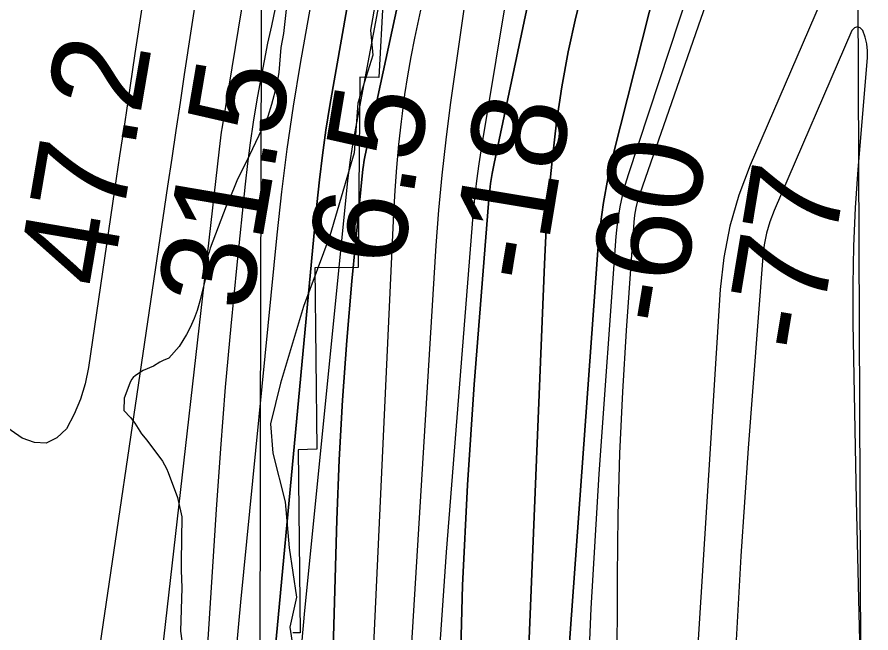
# Model space of a CAD drawing. Extents: x 3187622 to 3225504, y 800805 to 826213.
# Drawn here: x 3196898 to 3197502, y 822602 to 823038 of the extents above; entities that cross this region are included whole.
import ezdxf

# ---------------------------------------------------------------- set-up
doc = ezdxf.new("R2010")
doc.units = 0
for name, color, linetype in [('V-GRID-MAJR', 7, 'Continuous'), ('V-RIVR-EDGE', 7, 'Continuous'), ('V-RIVR-RANG', 7, 'Continuous'), ('V-RRAP-RVMT', 7, 'Continuous'), ('V-SITE-VEGE', 7, 'Continuous'), ('V-TOPO-DPTH', 7, 'Continuous'), ('V-TOPO-MAJR', 7, 'Continuous'), ('V-TOPO-MINR', 7, 'Continuous'), ('V-TOPO-WATR', 7, 'Continuous')]:
    doc.layers.add(name, color=color, linetype=linetype)

msp = doc.modelspace()

# ---------------------------------------------------------------- linework, layer by layer
at = {"layer": 'V-GRID-MAJR'}
msp.add_spline([(3197031.47, 806236.813), (3197045.574, 812297.071), (3197059.682, 818359.272), (3197073.789, 824421.511), (3197073.793, 824423.414)], degree=3, dxfattribs=at)
at = {"layer": 'V-RIVR-EDGE'}
msp.add_lwpolyline([(3197168.0925766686, 823307.4362562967), (3197151.0337839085, 823264.4451984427), (3197147.071178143, 823244.0250751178), (3197150.442182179, 823200.9835002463), (3197156.717268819, 823101.8611295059), (3197155.338001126, 823071.4369970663), (3197147.842091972, 823028.4222929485), (3197149.5367300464, 823010.5962559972), (3197139.0206566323, 822976.7172827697), (3197136.325536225, 822941.5149330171), (3197119.2280495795, 822882.8755201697), (3197100.4133534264, 822832.9339371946), (3197084.195968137, 822778.639139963), (3197077.1702049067, 822749.967686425), (3197078.8573191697, 822729.0989137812), (3197087.4659381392, 822694.7379714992), (3197090.428061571, 822662.1297081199), (3197095.55819349, 822627.3426879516), (3197090.724085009, 822606.055361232), (3197095.002061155, 822578.2253151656)], dxfattribs=at)
at = {"layer": 'V-RRAP-RVMT'}
for p, q in [((3197160.138000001, 823116.417999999), (3197153.893000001, 822994.8849999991)), ((3197495.440000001, 822468.317999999), (3197493.133000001, 823063.8709999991)), ((3197140.277000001, 822995.0219999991), (3197139.165000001, 822860.398999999)), ((3197153.893000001, 822994.8849999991), (3197140.277000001, 822995.0219999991)), ((3197139.165000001, 822860.398999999), (3197108.498000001, 822860.167999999)), ((3197108.498000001, 822860.167999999), (3197109.800000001, 822731.8879999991)), ((3197109.800000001, 822731.8879999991), (3197096.735000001, 822731.5619999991)), ((3197096.735000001, 822731.5619999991), (3197098.137000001, 822602.1149999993)), ((3197098.137000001, 822602.1149999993), (3197092.933000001, 822601.9669999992))]:
    msp.add_line(p, q, dxfattribs=at)
at = {"layer": 'V-SITE-VEGE'}
for p, q in [((3197090.024, 823060.696), (3197086.309, 823025.897)), ((3197086.309, 823025.897), (3197084.38, 823016.175)), ((3197084.38, 823016.175), (3197084.034, 823010.1089999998)), ((3197084.034, 823010.1089999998), (3197082.932, 822998.3740000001)), ((3197082.932, 822998.3740000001), (3197081.4020000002, 822989.061)), ((3197081.4020000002, 822989.061), (3197077.89, 822975.688)), ((3197077.89, 822975.688), (3197075.142, 822967.172)), ((3197075.142, 822967.172), (3197060.079, 822935.498)), ((3197057.697, 822931.029), (3197053.3370000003, 822921.6900000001)), ((3197060.079, 822935.498), (3197057.697, 822931.029)), ((3197053.3370000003, 822921.6900000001), (3197047.805, 822908.296)), ((3197047.805, 822908.296), (3197045.824, 822903.832)), ((3197045.824, 822903.832), (3197034.382, 822874.212)), ((3197033.6, 822871.375), (3197032.418, 822868.1290000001)), ((3197034.382, 822874.212), (3197033.6, 822871.375)), ((3197032.418, 822868.1290000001), (3197032.5100000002, 822858.4280000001)), ((3197032.5100000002, 822858.4280000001), (3197030.954, 822851.946)), ((3197030.954, 822851.946), (3197027.057, 822836.547)), ((3197027.057, 822836.547), (3197025.097, 822830.061)), ((3197025.097, 822830.061), (3197023.129, 822824.382)), ((3197023.129, 822824.382), (3197020.362, 822817.887)), ((3197020.362, 822817.887), (3197017.576, 822813.0089999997)), ((3197017.576, 822813.0089999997), (3197012.401, 822804.471)), ((3197012.401, 822804.471), (3197005.202, 822796.318)), ((3196998.761, 822793.4280000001), (3196994.342, 822790.557)), ((3197001.176, 822794.6630000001), (3196998.761, 822793.4280000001)), ((3197005.202, 822796.318), (3197001.176, 822794.6630000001)), ((3196987.094, 822787.659), (3196981.466, 822783.966)), ((3196994.342, 822790.557), (3196987.094, 822787.659)), ((3196978.666, 822781.109), (3196977.477, 822778.672)), ((3196979.862, 822782.736), (3196978.666, 822781.109)), ((3196981.466, 822783.966), (3196979.862, 822782.736)), ((3196977.477, 822778.672), (3196973.532, 822768.123)), ((3196973.532, 822768.123), (3196973.213, 822759.229)), ((3196973.213, 822759.229), (3196978.109, 822754.424)), ((3196978.109, 822754.424), (3196980.977, 822750.408)), ((3196980.977, 822750.408), (3196985.9, 822742.7729999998)), ((3196985.9, 822742.7729999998), (3196989.58, 822738.362)), ((3196989.58, 822738.362), (3197000.6350000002, 822723.509)), ((3197000.6350000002, 822723.509), (3197003.515, 822718.281)), ((3197003.515, 822718.281), (3197004.754, 822715.4629999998)), ((3197004.754, 822715.4629999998), (3197011.389, 822697.737)), ((3197011.389, 822697.737), (3197014.349, 822684.0219999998)), ((3197014.349, 822684.0219999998), (3197013.839, 822652.485)), ((3197013.839, 822652.485), (3197013.896, 822646.421)), ((3197013.896, 822646.421), (3197014.418, 822633.893)), ((3197014.418, 822633.893), (3197013.497, 822603.161)), ((3197013.497, 822603.161), (3197016.538, 822580.954))]:
    msp.add_line(p, q, dxfattribs=at)
at = {"layer": 'V-TOPO-DPTH'}
for points in [[(3197476.2531391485, 824082.4498993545), (3197400.6026303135, 823848.0940233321), (3197371.423133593, 823752.9000641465), (3197344.1403861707, 823657.1956286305), (3197319.702762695, 823560.7254786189), (3197297.1618885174, 823463.7448522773), (3197270.916225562, 823342.7248028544), (3197262.997966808, 823305.8549675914), (3197255.1788151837, 823268.9643345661), (3197247.5083242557, 823232.0425048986), (3197239.9369404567, 823195.0998774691), (3197232.7720213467, 823158.084515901), (3197226.0496171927, 823120.9930302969), (3197219.9909854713, 823083.7873586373), (3197214.3748687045, 823046.5055629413), (3197204.3212636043, 822975.4624295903), (3197201.1143222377, 822950.6746102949), (3197198.30237618, 822925.8468160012), (3197196.0829230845, 822900.9590592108), (3197194.2584652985, 822876.0313274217), (3197159.798511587, 822313.1102253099)], [(3197476.2531391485, 824082.4498993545), (3197400.6026303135, 823848.0940233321), (3197371.423133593, 823752.9000641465), (3197344.1403861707, 823657.1956286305), (3197319.702762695, 823560.7254786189), (3197297.1618885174, 823463.7448522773), (3197270.916225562, 823342.7248028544), (3197262.997966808, 823305.8549675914), (3197255.1788151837, 823268.9643345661), (3197247.5083242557, 823232.0425048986), (3197239.9369404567, 823195.0998774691), (3197232.7720213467, 823158.084515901), (3197226.0496171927, 823120.9930302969), (3197219.9909854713, 823083.7873586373), (3197214.3748687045, 823046.5055629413), (3197204.3212636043, 822975.4624295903), (3197201.1143222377, 822950.6746102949), (3197198.30237618, 822925.8468160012), (3197196.0829230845, 822900.9590592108), (3197194.2584652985, 822876.0313274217), (3197159.798511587, 822313.1102253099)], [(3197242.8272081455, 822171.8038128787), (3197270.9694217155, 822862.7606196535), (3197272.3360784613, 822887.9559272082), (3197274.154351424, 822913.1124672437), (3197276.6500487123, 822938.210856), (3197279.5973622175, 822963.270477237), (3197283.3806034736, 822988.2016909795), (3197287.8235845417, 823013.0010180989), (3197293.256175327, 823037.6025152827), (3197299.3485059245, 823062.072125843), (3197311.6804694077, 823107.6837639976), (3197324.16746818, 823154.9269685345), (3197336.297293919, 823202.2595570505), (3197347.89136011, 823249.7262215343), (3197359.1282532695, 823297.2822699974), (3197392.6230658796, 823442.7045141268), (3197414.0540988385, 823540.5690377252), (3197434.0696880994, 823638.7063679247), (3197451.962111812, 823737.252908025), (3197468.4390918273, 823836.0722547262), (3197497.127014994, 824020.3690957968)], [(3197497.127014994, 824020.3690957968), (3197468.4390918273, 823836.0722547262), (3197451.962111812, 823737.252908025), (3197434.0696880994, 823638.7063679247), (3197414.0540988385, 823540.5690377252), (3197392.6230658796, 823442.7045141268), (3197359.1282532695, 823297.2822699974), (3197347.89136011, 823249.7262215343), (3197336.297293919, 823202.2595570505), (3197324.16746818, 823154.9269685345), (3197311.6804694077, 823107.6837639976), (3197299.3485059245, 823062.072125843), (3197293.256175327, 823037.6025152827), (3197287.8235845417, 823013.0010180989), (3197283.3806034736, 822988.2016909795), (3197279.5973622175, 822963.270477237), (3197276.6500487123, 822938.210856), (3197274.154351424, 822913.1124672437), (3197272.3360784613, 822887.9559272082), (3197270.9694217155, 822862.7606196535), (3197242.8272081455, 822171.8038128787)], [(3197103.322574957, 821953.4703882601), (3197124.125590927, 822682.0580161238), (3197125.7716292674, 822724.3229395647), (3197128.0017201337, 822766.55093606), (3197131.1078897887, 822808.7235421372), (3197134.7981119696, 822850.8592212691), (3197142.564255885, 822930.0649157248), (3197142.8528429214, 822932.5633014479), (3197143.1985527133, 822935.0527473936), (3197143.6299466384, 822937.5287836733), (3197144.118463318, 822939.9958801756), (3197198.8532792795, 823193.3804697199), (3197227.1892405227, 823322.433536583), (3197256.1079080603, 823451.3538161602), (3197285.900635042, 823580.0749148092), (3197316.27606832, 823708.6632261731), (3197380.5428862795, 823976.6569945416)], [(3197380.5428862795, 823976.6569945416), (3197316.27606832, 823708.6632261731), (3197285.900635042, 823580.0749148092), (3197256.1079080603, 823451.3538161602), (3197227.1892405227, 823322.433536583), (3197198.8532792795, 823193.3804697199), (3197144.118463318, 822939.9958801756), (3197143.6299466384, 822937.5287836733), (3197143.1985527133, 822935.0527473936), (3197142.8528429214, 822932.5633014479), (3197142.564255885, 822930.0649157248), (3197134.7981119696, 822850.8592212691), (3197131.1078897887, 822808.7235421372), (3197128.0017201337, 822766.55093606), (3197125.7716292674, 822724.3229395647), (3197124.125590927, 822682.0580161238), (3197103.322574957, 821953.4703882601)], [(3197281.5857899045, 822497.2418799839), (3197308.8040364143, 822872.4387211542), (3197310.4971456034, 822889.5325576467), (3197312.7835355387, 822906.5306580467), (3197315.959846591, 822923.3851543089), (3197319.72943839, 822940.1439144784), (3197365.746160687, 823122.2127291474), (3197393.0135693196, 823229.9230522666), (3197420.3365011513, 823337.6192660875), (3197447.742717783, 823445.2943159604), (3197475.204457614, 823552.9552565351), (3197577.42040236, 823953.0363443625)], [(3197577.42040236, 823953.0363443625), (3197475.204457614, 823552.9552565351), (3197447.742717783, 823445.2943159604), (3197420.3365011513, 823337.6192660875), (3197393.0135693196, 823229.9230522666), (3197365.746160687, 823122.2127291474), (3197319.72943839, 822940.1439144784), (3197315.959846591, 822923.3851543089), (3197312.7835355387, 822906.5306580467), (3197310.4971456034, 822889.5325576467), (3197308.8040364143, 822872.4387211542), (3197281.5857899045, 822497.2418799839)], [(3197020.704210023, 821952.4745692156), (3197109.8662032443, 822904.9091030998), (3197111.7212363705, 822922.4788250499), (3197113.852775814, 822940.0116019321), (3197116.3990747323, 822957.4889612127), (3197119.2218799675, 822974.9293754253), (3197139.3290842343, 823090.4632308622), (3197151.951864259, 823159.7168864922), (3197165.3085295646, 823228.8226149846), (3197179.7660227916, 823297.7064527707), (3197194.957401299, 823366.4423634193), (3197210.47413456, 823435.1163804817), (3197225.690386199, 823503.855880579), (3197240.4559154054, 823572.6936052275), (3197254.9209629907, 823641.59681291), (3197255.4869191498, 823644.3373265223), (3197270.757425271, 823714.477394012), (3197287.024024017, 823784.3743678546), (3197304.7847616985, 823853.9067012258), (3197323.541592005, 823923.1959409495)], [(3197211.028220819, 822564.1716748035), (3197212.9280567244, 822635.4363395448), (3197216.5321678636, 822706.6351611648), (3197221.2724624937, 822777.7900873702), (3197231.33293615, 822905.70868959), (3197232.0349290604, 822912.851330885), (3197232.921164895, 822919.9673742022), (3197234.083765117, 822927.0435205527), (3197235.4306082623, 822934.0930689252), (3197296.2809996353, 823222.0408741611), (3197311.7490204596, 823296.6345509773), (3197326.839001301, 823371.303135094), (3197341.3619221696, 823446.0840801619), (3197355.506803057, 823520.9399325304), (3197365.6595967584, 823575.8096613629), (3197374.5794362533, 823623.2605452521), (3197383.6791599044, 823670.6763757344), (3197393.048709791, 823718.0396261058), (3197402.5981438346, 823765.3678230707), (3197413.056031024, 823812.4663594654), (3197424.542680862, 823859.2944241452)], [(3197424.542680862, 823859.2944241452), (3197413.056031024, 823812.4663594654), (3197402.5981438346, 823765.3678230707), (3197393.048709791, 823718.0396261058), (3197383.6791599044, 823670.6763757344), (3197374.5794362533, 823623.2605452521), (3197365.6595967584, 823575.8096613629), (3197355.506803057, 823520.9399325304), (3197341.3619221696, 823446.0840801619), (3197326.839001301, 823371.303135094), (3197311.7490204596, 823296.6345509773), (3197296.2809996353, 823222.0408741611), (3197235.4306082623, 822934.0930689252), (3197234.083765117, 822927.0435205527), (3197232.921164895, 822919.9673742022), (3197232.0349290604, 822912.851330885), (3197231.33293615, 822905.70868959), (3197221.2724624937, 822777.7900873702), (3197216.5321678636, 822706.6351611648), (3197212.9280567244, 822635.4363395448), (3197211.028220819, 822564.1716748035)]]:
    msp.add_lwpolyline(points, dxfattribs=at)
at = {"layer": 'V-TOPO-MAJR'}
for points in [[(3197160.9858875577, 823919.8181040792), (3197122.730055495, 823481.4339728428), (3197118.5188925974, 823443.2658866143), (3197117.436540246, 823434.5973363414), (3197111.8903320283, 823392.1723986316), (3197106.018048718, 823349.7945660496), (3197099.65665277, 823307.4873911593), (3197092.9691817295, 823265.2273213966), (3197042.856573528, 822959.9820905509), (3197042.2429021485, 822956.0605886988), (3197041.6684870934, 822952.1336445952), (3197041.1529565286, 822948.1985371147), (3197040.6766822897, 822944.2579873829), (3196999.0563170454, 822576.8207611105)], [(3197637.641892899, 823857.4842518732), (3197627.7100389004, 823827.822168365), (3197330.1723853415, 822926.0427880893), (3197327.0736734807, 822915.3281420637), (3197324.514463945, 822904.5068658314), (3197322.764507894, 822893.5256442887), (3197321.5540541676, 822882.4377925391), (3197309.5101813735, 822714.4281206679), (3197303.874633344, 822619.218688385), (3197299.8195319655, 822523.96166052)]]:
    msp.add_lwpolyline(points, dxfattribs=at)
at = {"layer": 'V-TOPO-MINR'}
for points in [[(3197476.2531391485, 824082.4498993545), (3197400.6026303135, 823848.0940233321), (3197371.423133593, 823752.9000641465), (3197344.1403861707, 823657.1956286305), (3197319.702762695, 823560.7254786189), (3197297.1618885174, 823463.7448522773), (3197270.916225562, 823342.7248028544), (3197262.997966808, 823305.8549675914), (3197255.1788151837, 823268.9643345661), (3197247.5083242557, 823232.0425048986), (3197239.9369404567, 823195.0998774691), (3197232.7720213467, 823158.084515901), (3197226.0496171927, 823120.9930302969), (3197219.9909854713, 823083.7873586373), (3197214.3748687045, 823046.5055629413), (3197204.3212636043, 822975.4624295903), (3197201.1143222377, 822950.6746102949), (3197198.30237618, 822925.8468160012), (3197196.0829230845, 822900.9590592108), (3197194.2584652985, 822876.0313274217), (3197159.798511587, 822313.1102253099)], [(3197442.105376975, 824067.35432897), (3197368.953446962, 823808.4599274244), (3197334.592767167, 823682.8284799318), (3197301.6463440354, 823556.8398657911), (3197270.821305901, 823430.3155016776), (3197241.4105244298, 823303.4339709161), (3197190.5959848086, 823075.5262056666), (3197187.6756980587, 823062.3257643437), (3197184.784529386, 823049.1189990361), (3197181.937037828, 823035.9027477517), (3197179.1186643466, 823022.6801724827), (3197176.4985662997, 823009.423603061), (3197174.1133364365, 822996.1280952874), (3197172.0804088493, 822982.7741799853), (3197170.2823494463, 822969.3813263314), (3197169.6016747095, 822963.7474107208), (3197167.8206250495, 822947.4932505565), (3197166.280515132, 822931.2189830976), (3197165.101814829, 822914.9145546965), (3197164.1640542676, 822898.590019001), (3197119.64, 821937.36)], [(3197497.127014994, 824020.3690957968), (3197468.4390918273, 823836.0722547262), (3197451.962111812, 823737.252908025), (3197434.0696880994, 823638.7063679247), (3197414.0540988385, 823540.5690377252), (3197392.6230658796, 823442.7045141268), (3197359.1282532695, 823297.2822699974), (3197347.89136011, 823249.7262215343), (3197336.297293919, 823202.2595570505), (3197324.16746818, 823154.9269685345), (3197311.6804694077, 823107.6837639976), (3197299.3485059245, 823062.072125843), (3197293.256175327, 823037.6025152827), (3197287.8235845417, 823013.0010180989), (3197283.3806034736, 822988.2016909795), (3197279.5973622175, 822963.270477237), (3197276.6500487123, 822938.210856), (3197274.154351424, 822913.1124672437), (3197272.3360784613, 822887.9559272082), (3197270.9694217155, 822862.7606196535), (3197242.8272081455, 822171.8038128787)], [(3197288.068950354, 824005.5007477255), (3197256.8138557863, 823823.5362040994), (3197240.682622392, 823731.7070649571), (3197224.088511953, 823639.9634599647), (3197206.8000859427, 823548.3481561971), (3197189.048782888, 823456.8183865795), (3197168.363838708, 823352.2815286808), (3197160.4596955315, 823313.1156020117), (3197152.3581008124, 823273.9913429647), (3197143.9603287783, 823234.9295853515), (3197135.365105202, 823195.9094953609), (3197126.9058020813, 823156.8641339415), (3197118.825019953, 823117.7434407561), (3197111.3120193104, 823078.5097499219), (3197104.1775396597, 823039.2007273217), (3197098.1691483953, 823004.6740041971), (3197093.2587021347, 822974.4867137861), (3197088.7942141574, 822944.2386246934), (3197084.998663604, 822913.8993375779), (3197081.649071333, 822883.499251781), (3197055.9243603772, 822623.7069545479), (3197045.18181138, 822508.7010411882)], [(3197577.42040236, 823953.0363443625), (3197475.204457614, 823552.9552565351), (3197447.742717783, 823445.2943159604), (3197420.3365011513, 823337.6192660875), (3197393.0135693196, 823229.9230522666), (3197365.746160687, 823122.2127291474), (3197319.72943839, 822940.1439144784), (3197315.959846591, 822923.3851543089), (3197312.7835355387, 822906.5306580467), (3197310.4971456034, 822889.5325576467), (3197308.8040364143, 822872.4387211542), (3197281.5857899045, 822497.2418799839)], [(3197323.541592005, 823923.1959409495), (3197304.7847616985, 823853.9067012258), (3197287.024024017, 823784.3743678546), (3197270.757425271, 823714.477394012), (3197255.4869191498, 823644.3373265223), (3197254.9209629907, 823641.59681291), (3197240.4559154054, 823572.6936052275), (3197225.690386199, 823503.855880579), (3197210.47413456, 823435.1163804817), (3197194.957401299, 823366.4423634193), (3197179.7660227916, 823297.7064527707), (3197165.3085295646, 823228.8226149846), (3197151.951864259, 823159.7168864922), (3197139.3290842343, 823090.4632308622), (3197119.2218799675, 822974.9293754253), (3197116.3990747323, 822957.4889612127), (3197113.852775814, 822940.0116019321), (3197111.7212363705, 822922.4788250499), (3197109.8662032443, 822904.9091030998), (3197020.704210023, 821952.4745692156)], [(3197425.211009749, 823897.1767191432), (3197404.0428047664, 823827.9027550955), (3197384.3368996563, 823758.239793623), (3197366.8244443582, 823687.993336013), (3197350.7742889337, 823617.3578809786), (3197344.967522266, 823589.8103305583), (3197333.0578975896, 823532.6283198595), (3197321.3321628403, 823475.4090866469), (3197309.8822629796, 823418.1340196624), (3197298.616253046, 823360.8217301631), (3197287.7201065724, 823303.4397380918), (3197277.1331649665, 823246.0020421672), (3197267.0100306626, 823188.480790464), (3197257.1961012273, 823130.903834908), (3197226.4387604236, 822945.9527901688), (3197224.579252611, 822933.8197166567), (3197222.9261673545, 822921.6612458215), (3197221.58271593, 822909.4646790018), (3197220.445687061, 822897.2427148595), (3197201.348804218, 822659.1872733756), (3197193.235318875, 822539.5192416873)], [(3197334.52754765, 823884.5817722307), (3197324.2564548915, 823839.1283988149), (3197314.335074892, 823793.5833977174), (3197304.2431112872, 823748.0767305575), (3197293.895272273, 823702.6275643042), (3197283.3768496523, 823657.2167319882), (3197255.9727221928, 823540.4016736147), (3197233.191810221, 823440.2798583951), (3197211.308802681, 823339.9684613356), (3197190.772651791, 823239.372691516), (3197171.1344053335, 823138.5873398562), (3197135.979603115, 822951.4965842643), (3197134.688045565, 822944.1006111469), (3197133.5237323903, 822936.6863277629), (3197132.550285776, 822929.2445789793), (3197131.7040835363, 822921.7845199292), (3197101.1686302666, 822617.7487396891), (3197090.999860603, 822504.2477903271)], [(3197424.542680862, 823859.2944241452), (3197413.056031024, 823812.4663594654), (3197402.5981438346, 823765.3678230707), (3197393.048709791, 823718.0396261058), (3197383.6791599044, 823670.6763757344), (3197374.5794362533, 823623.2605452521), (3197365.6595967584, 823575.8096613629), (3197355.506803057, 823520.9399325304), (3197341.3619221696, 823446.0840801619), (3197326.839001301, 823371.303135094), (3197311.7490204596, 823296.6345509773), (3197296.2809996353, 823222.0408741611), (3197235.4306082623, 822934.0930689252), (3197234.083765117, 822927.0435205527), (3197232.921164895, 822919.9673742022), (3197232.0349290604, 822912.851330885), (3197231.33293615, 822905.70868959), (3197221.2724624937, 822777.7900873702), (3197216.5321678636, 822706.6351611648), (3197212.9280567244, 822635.4363395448), (3197211.028220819, 822564.1716748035)], [(3197140.897697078, 823361.7732932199), (3197087.831010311, 823081.0356448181), (3197085.4257334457, 823068.6061619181), (3197082.948853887, 823056.1912870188), (3197080.3645702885, 823043.7983241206), (3197077.708683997, 823031.4199692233), (3197075.079905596, 823019.0366933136), (3197072.55884397, 823006.6322538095), (3197070.199357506, 822994.1960689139), (3197067.947587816, 822981.7387204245), (3197067.241438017, 822977.681526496), (3197064.868693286, 822963.1587297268), (3197062.6974552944, 822948.6079975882), (3197060.828477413, 822934.0153623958), (3197059.1610062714, 822919.3947918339), (3197053.246108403, 822862.2758280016), (3197049.025601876, 822819.0535679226), (3197045.1424990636, 822775.8030032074), (3197041.7655018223, 822732.509981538), (3197038.7259082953, 822689.1886552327), (3196991.953011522, 821961.6502314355)], [(3197501.9231180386, 823338.6643581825), (3197463.69874119, 823253.5462186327), (3197428.931769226, 823166.9583538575), (3197396.469733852, 823079.3906722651), (3197338.4232203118, 822912.5718315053), (3197336.9222589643, 822907.6342816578), (3197335.6875570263, 822902.6419810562), (3197334.8522442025, 822897.5675543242), (3197334.2831907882, 822892.4383768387), (3197328.8565421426, 822815.8619254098), (3197326.218754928, 822772.3865304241), (3197324.1697032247, 822728.8893860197), (3197323.0037547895, 822685.3596174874), (3197322.4265418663, 822641.8080995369), (3197320.4110162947, 821992.5032210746)], [(3197053.8124087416, 823297.5677973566), (3197053.6251227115, 823274.4110408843), (3197052.2476790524, 823251.2179907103), (3197049.7811826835, 823228.020374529), (3197047.0693980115, 823204.8534486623), (3197043.9896808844, 823181.7325582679), (3197040.6646754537, 823158.6423581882), (3197016.0581492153, 822996.889702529), (3197013.0714621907, 822977.1672631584), (3197010.1024747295, 822957.4421718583), (3197007.160036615, 822937.7131026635), (3197004.235298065, 822917.9813815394), (3196942.1599666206, 822497.2388723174)], [(3197565.8956859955, 823278.5751856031), (3197416.5236298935, 822932.9353806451), (3197408.5696266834, 822911.5344941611), (3197402.141377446, 822889.7678353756), (3197398.001759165, 822867.4525181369), (3197395.387894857, 822844.7714285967), (3197365.253328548, 822364.502108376)], [(3196986.1153376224, 823044.0022770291), (3196981.201917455, 823011.7021633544), (3196977.5546442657, 822987.6167633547), (3196973.9289372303, 822963.5281321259), (3196970.3355794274, 822939.434654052), (3196966.7637877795, 822915.3379447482), (3196948.2167508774, 822789.6305053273), (3196945.8359819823, 822778.2683081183), (3196942.592250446, 822767.2164652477), (3196938.0540749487, 822756.6301538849), (3196932.6529368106, 822746.3541968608), (3196925.8158346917, 822739.9272726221), (3196918.4007069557, 822736.2194798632), (3196910.1185407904, 822736.5903843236), (3196901.258349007, 822739.680420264), (3196854.3138544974, 822772.3437008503)], [(3197496.449962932, 822516.1258658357), (3197493.9847616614, 822605.9493468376), (3197491.9751908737, 822695.7870676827), (3197489.6485542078, 822821.1284283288), (3197489.55384471, 822848.2931715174), (3197490.004353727, 822875.4406461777), (3197491.2726905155, 822902.5622180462), (3197493.086245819, 822929.6665213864), (3197499.569398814, 823008.6638969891), (3197499.6165524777, 823013.6472237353), (3197499.1976368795, 823018.5567672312), (3197498.07961739, 823023.3556358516), (3197496.4955286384, 823028.080721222), (3197494.527890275, 823029.925153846), (3197492.5539565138, 823030.7224223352), (3197490.5705796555, 823029.9489446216), (3197488.5809073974, 823028.128302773), (3197433.5099881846, 822900.6971294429), (3197430.5593228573, 822892.8082651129), (3197428.1486480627, 822884.7860567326), (3197426.547959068, 822876.5638322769), (3197425.4872606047, 822868.2082637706), (3197415.1226377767, 822732.5738442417), (3197409.971314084, 822656.2670641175), (3197405.72240771, 822579.9180806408)]]:
    msp.add_lwpolyline(points, dxfattribs=at)
at = {"layer": 'V-TOPO-WATR'}
msp.add_lwpolyline([(3197380.5428862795, 823976.6569945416), (3197316.27606832, 823708.6632261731), (3197285.900635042, 823580.0749148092), (3197256.1079080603, 823451.3538161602), (3197227.1892405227, 823322.433536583), (3197198.8532792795, 823193.3804697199), (3197144.118463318, 822939.9958801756), (3197143.6299466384, 822937.5287836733), (3197143.1985527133, 822935.0527473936), (3197142.8528429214, 822932.5633014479), (3197142.564255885, 822930.0649157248), (3197134.7981119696, 822850.8592212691), (3197131.1078897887, 822808.7235421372), (3197128.0017201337, 822766.55093606), (3197125.7716292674, 822724.3229395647), (3197124.125590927, 822682.0580161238), (3197103.322574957, 821953.4703882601)], dxfattribs=at)

# ---------------------------------------------------------------- texts
at = {"layer": 'V-RIVR-RANG'}
for s, rotation, p in [('47.2', 80.30832571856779, (3196963.827066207, 822844.7757212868)), ('31.5', 80.30832571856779, (3197062.441066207, 822828.1847212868)), ('6.5', 80.61413888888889, (3197169.581757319, 822859.2914769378)), ('-18', 80.61413888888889, (3197269.056113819, 822847.9054401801)), ('-60', 80.61413888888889, (3197365.390169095, 822817.5222875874)), ('-77', 80.61413888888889, (3197463.61800867, 822798.5890541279))]:
    msp.add_text(s, height=67, rotation=rotation, dxfattribs=at).set_placement(p)

doc.saveas('drawing.dxf')
